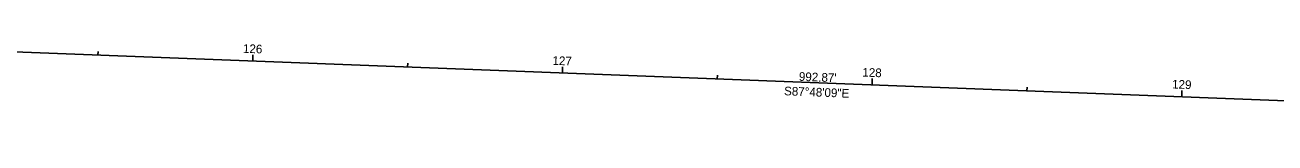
# Model space of a CAD drawing. Extents: x 2003596 to 2006888, y 572582 to 572983.
# Drawn here: x 2005260.9 to 2005664.2, y 572597.3 to 572635.3 of the extents above; entities that cross this region are included whole.
import ezdxf

# ---------------------------------------------------------------- set-up
doc = ezdxf.new("R2010")
doc.units = 0
for name, color, linetype in [('DR_X_Ditch', 7, 'Continuous'), ('PM_X_CL_Double_Solid', 7, 'Continuous'), ('PM_X_Edge_Line', 7, 'Continuous'), ('PM_X_Surveyed_Line', 7, 'Continuous'), ('PV_X_EOP', 7, 'Continuous'), ('RD_X_Fence', 7, 'Continuous'), ('SV_X_Break_Lines', 7, 'Continuous'), ('UT_X_Water', 7, 'Continuous'), ('XS_X_Ground_Line', 7, 'Continuous')]:
    doc.layers.add(name, color=color, linetype=linetype)

msp = doc.modelspace()

# ---------------------------------------------------------------- linework, layer by layer
at = {"layer": 'DR_X_Ditch'}
for p, q in [((2005284.36, 572625.62), (2005284.41, 572626.82)), ((2005334.33, 572623.7), (2005334.4, 572625.7)), ((2005384.29, 572621.78), (2005384.34, 572622.98)), ((2005434.25, 572619.86), (2005434.33, 572621.86)), ((2005484.22, 572617.95), (2005484.26, 572619.15)), ((2005534.18, 572616.03), (2005534.26, 572618.03)), ((2005584.14, 572614.11), (2005584.19, 572615.31)), ((2005634.11, 572612.2), (2005634.18, 572614.19))]:
    msp.add_line(p, q, dxfattribs=at)
at = {"layer": 'PM_X_Surveyed_Line'}
msp.add_line((2005031.48, 572635.32), (2006023.62, 572597.25), dxfattribs=at)
at = {"layer": 'RD_X_Fence'}
for p, q in [((2005334.33, 572623.7), (2005334.37, 572624.9)), ((2005434.25, 572619.86), (2005434.3, 572621.06)), ((2005534.18, 572616.03), (2005534.23, 572617.23)), ((2005634.11, 572612.2), (2005634.15, 572613.4))]:
    msp.add_line(p, q, dxfattribs=at)

# ---------------------------------------------------------------- texts
at = {"layer": 'DR_X_Ditch'}
for s, p in [('126', (2005331.14, 572626.37)), ('127', (2005431.01, 572622.49)), ('128', (2005531, 572618.7)), ('129', (2005630.95, 572614.87))]:
    msp.add_text(s, height=2.8, rotation=357.8026, dxfattribs=at).set_placement(p)
at = {"layer": 'PM_X_CL_Double_Solid'}
msp.add_text("992.87'", height=2.8, rotation=357.8026, dxfattribs=at).set_placement((2005510.52, 572617.33))
at = {"layer": 'PM_X_Edge_Line'}
msp.add_text("992.87'", height=2.8, rotation=357.8026, dxfattribs=at).set_placement((2005510.52, 572617.33))
at = {"layer": 'PV_X_EOP'}
msp.add_text('S87°48\'09"E', height=2.8, rotation=357.8026, dxfattribs=at).set_placement((2005505.75, 572612.66))
at = {"layer": 'SV_X_Break_Lines'}
msp.add_text('S87°48\'09"E', height=2.8, rotation=357.8026, dxfattribs=at).set_placement((2005505.75, 572612.66))
at = {"layer": 'UT_X_Water'}
msp.add_text('S87°48\'09"E', height=2.8, rotation=357.8026, dxfattribs=at).set_placement((2005505.75, 572612.66))
at = {"layer": 'XS_X_Ground_Line'}
msp.add_text("992.87'", height=2.8, rotation=357.8026, dxfattribs=at).set_placement((2005510.52, 572617.33))

doc.saveas('drawing.dxf')
